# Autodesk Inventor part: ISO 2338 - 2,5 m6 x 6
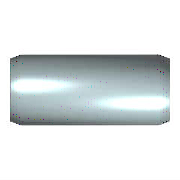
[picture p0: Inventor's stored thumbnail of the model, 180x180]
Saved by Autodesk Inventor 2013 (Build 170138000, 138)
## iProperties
Created: 2012-02
Part Number: ISO 2338 - 2,5 m6 x 6
Material: Stainless Steel, Austenitic
Description: Parallel Pin
Document SubType Name: Modeling
Standard: ISO 2338
Designer: rYan
Standards Organization: DIN
Language: en-US
Size Designation: 2,5 m6 x 6
Categories: <MemberInstance><Categories><Category DisplayName="Fasteners" InternalName="e4da775c-781d-43d5-af7c-5136215cf5a6" Mnemonic="FSTN"><Category DisplayName="Pins" I
Density: 8.03 g/cm^3
IsCustomPart: 0
Author: rYan
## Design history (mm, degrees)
sketch "Sketch"
  geometry: C1 r 1.25 at (0, 0); 1 further point
  constraints: 1 centre point, 1 coincident
  dimensions: "d1" = 2.5 diameter of C1 (= NND)
extrude "Body" new body sketch "Sketch" distance "d2" = 6 (= NLG); taper "d3" = 0 deg
body "Solid1"
chamfer "Chamfer1" distance "d4" = 0.4 (= PHH); stored, may be unused: angle "d5" = 15 deg (= FAWI), second distance "d11" = 0.4 (= PHH)
chamfer "Chamfer2" distance "d8" = 0.4 (= PHH); stored, may be unused: angle "d9" = 15 deg (= FAWI), second distance "d12" = 0.4 (= PHH)
other parameters: "NND" = 2.5 [user parameter; used in 1 equation term], "NLG" = 6 [user parameter; used in 1 equation term], "PHH" = 0.4 [user parameter; used in 4 equation terms], "FAWI" = 15 deg [user parameter; used in 2 equation terms], "d13" = 0, "d15" = 0, "d16" = 0, "KAH" = 0 [user parameter]
